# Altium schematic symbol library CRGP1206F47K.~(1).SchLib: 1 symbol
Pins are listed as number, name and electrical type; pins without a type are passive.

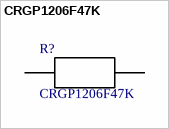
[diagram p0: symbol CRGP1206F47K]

## CRGP1206F47K
designator R?
footprint *RESC3115X65N
pins: 1, 2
